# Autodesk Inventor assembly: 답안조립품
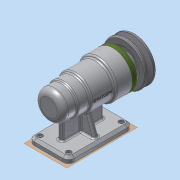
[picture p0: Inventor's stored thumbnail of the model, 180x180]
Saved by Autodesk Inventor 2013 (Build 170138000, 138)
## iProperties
Created: 2016-06
Part Number: 답안조립품
Document SubType Name: Assembly
Designer: dgall
Author: dgall
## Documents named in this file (12)
- C:\Users\dgall\Desktop\460607V1013\답안조립품.iam
- C:\Users\dgall\Desktop\460607V1013\본체.ipt
- C:\Users\dgall\Desktop\460607V1013\V벨트풀리.ipt
- C:\Users\dgall\Desktop\460607V1013\멈춤나사 M3x8.ipt
- C:\Users\dgall\Desktop\460607V1013\베어링 6004.ipt
- C:\Users\dgall\Desktop\460607V1013\베어링 51202.ipt
- C:\Users\dgall\Desktop\460607V1013\볼트 M4 x 12.ipt
- C:\Users\dgall\Desktop\460607V1013\어댑터슬리브.ipt
- C:\Users\dgall\Desktop\460607V1013\오일 실.ipt
- C:\Users\dgall\Desktop\460607V1013\축.ipt
- C:\Users\dgall\Desktop\460607V1013\커버.ipt
- C:\Users\dgall\Desktop\460607V1013\키 5 x 5 x 16.ipt
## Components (6 placed, 2 different names)
1. V벨트풀리:1
2. ISO 4762 M4 x 12:1
3. ISO 4762 M4 x 12:2
4. ISO 4762 M4 x 12:3
5. ISO 4762 M4 x 12:4
6. ISO 4762 M4 x 12:5
